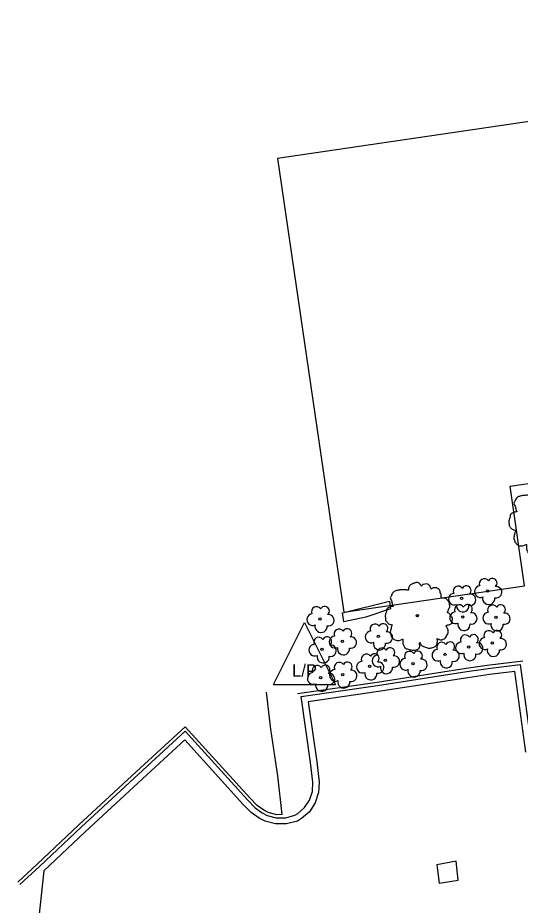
# Model space of a CAD drawing. Extents: x 2161152 to 2175754, y 602179 to 617749.
# Drawn here: x 2163456.9 to 2163537.9, y 606200.3 to 606343.4 of the extents above; entities that cross this region are included whole.
import ezdxf

# ---------------------------------------------------------------- set-up
doc = ezdxf.new("R2010")
doc.units = 0
for name, color, linetype in [('RD_EX_Bldg', 7, 'Continuous'), ('RD_EX_Conc_Curb', 7, 'Continuous'), ('RD_EX_Conc_Gutter', 7, 'Continuous'), ('RD_EX_Conc_Sidewalk', 7, 'Continuous'), ('RD_EX_DR_Inlet', 7, 'Continuous'), ('RD_EX_UT', 7, 'Continuous'), ('RD_EX_VEG', 7, 'Continuous')]:
    doc.layers.add(name, color=color, linetype=linetype)

msp = doc.modelspace()

# ---------------------------------------------------------------- linework, layer by layer
at = {"layer": 'RD_EX_Bldg'}
msp.add_lwpolyline([(2163498.74, 606320.78), (2163509.48, 606247.58), (2163538.63, 606251.86), (2163536.27, 606267.93), (2163632.21, 606282.02), (2163634.56, 606266.02), (2163663.95, 606270.34), (2163653.22, 606343.45), (2163498.74, 606320.78)], dxfattribs=at)
at = {"layer": 'RD_EX_Conc_Curb'}
for points in [[(2163457.2, 606203.69), (2163460.34, 606206.62), (2163467.07, 606212.93), (2163477.02, 606222.12), (2163483.86, 606228.43), (2163493.91, 606217.34), (2163495.17, 606216.05), (2163496.29, 606215.23), (2163497.1, 606214.83), (2163498.57, 606214.45), (2163500.1, 606214.46), (2163501.58, 606214.86), (2163502.04, 606215.13), (2163503.14, 606216.09), (2163503.95, 606217.31), (2163504.4, 606218.7), (2163504.47, 606220.17), (2163504.11, 606223.35), (2163502.57, 606234.01), (2163514.92, 606235.8), (2163529.3, 606238.03), (2163532.75, 606238.53), (2163537.89, 606239.18), (2163539.78, 606225.31)], [(2163538.32, 606239.73), (2163532.57, 606239.01), (2163529.22, 606238.52), (2163514.84, 606236.29), (2163502.01, 606234.44)], [(2163499.53, 606214.96), (2163498.64, 606214.95), (2163497.27, 606215.31), (2163496.55, 606215.66), (2163495.49, 606216.43), (2163494.28, 606217.68), (2163483.89, 606229.14), (2163476.68, 606222.49), (2163466.72, 606213.29), (2163460, 606206.98), (2163456.86, 606204.06)]]:
    msp.add_lwpolyline(points, dxfattribs=at)
at = {"layer": 'RD_EX_Conc_Gutter'}
msp.add_lwpolyline([(2163538.81, 606225.05), (2163537.04, 606238.06), (2163532.97, 606237.55), (2163529.45, 606237.04), (2163515.07, 606234.81), (2163503.71, 606233.17), (2163505.1, 606223.48), (2163505.47, 606220.2), (2163505.39, 606218.52), (2163504.86, 606216.87), (2163503.9, 606215.43), (2163502.63, 606214.32), (2163501.97, 606213.93), (2163500.24, 606213.46), (2163498.45, 606213.45), (2163496.75, 606213.89), (2163495.78, 606214.37), (2163494.51, 606215.29), (2163493.18, 606216.65), (2163483.8, 606227.01), (2163477.7, 606221.38), (2163467.75, 606212.19), (2163461.04, 606205.9), (2163460.26, 606198.45)], dxfattribs=at)
at = {"layer": 'RD_EX_Conc_Sidewalk'}
msp.add_lwpolyline([(2163499.53, 606214.96), (2163498.81, 606221.23), (2163497.69, 606228.72), (2163497, 606234.68)], dxfattribs=at)
at = {"layer": 'RD_EX_DR_Inlet'}
msp.add_lwpolyline([(2163524.44, 606206.89), (2163524.86, 606203.92), (2163527.91, 606204.39), (2163527.57, 606207.45), (2163524.44, 606206.89)], dxfattribs=at)
at = {"layer": 'RD_EX_UT'}
for p, q in [((2163498.13, 606235.92), (2163503.13, 606245.92)), ((2163503.13, 606245.92), (2163508.13, 606235.92)), ((2163498.13, 606235.92), (2163508.13, 606235.92))]:
    msp.add_line(p, q, dxfattribs=at)
at = {"layer": 'RD_EX_VEG'}
msp.add_lwpolyline([(2163513.02, 606246.78), (2163509.46, 606246.05), (2163509.27, 606247.49), (2163516.84, 606249.36), (2163516.97, 606248.13), (2163513.02, 606246.78)], dxfattribs=at)
for centre, radius in [((2163532.66, 606251.03), 0.188), ((2163528.46, 606249.82), 0.188), ((2163505.6, 606246.52), 0.188), ((2163521.33, 606247.02), 0.188), ((2163521.32, 606247.01), 0.000075), ((2163528.66, 606246.81), 0.188), ((2163534, 606246.77), 0.188), ((2163515.04, 606243.72), 0.188), ((2163505.95, 606241.59), 0.188), ((2163509.23, 606242.91), 0.188), ((2163529.61, 606241.97), 0.188), ((2163533.41, 606242.65), 0.188), ((2163525.8, 606240.78), 0.188), ((2163513.63, 606238.87), 0.188), ((2163516.16, 606239.86), 0.188), ((2163520.61, 606239.32), 0.188), ((2163509.28, 606237.55), 0.188), ((2163505.7, 606237.04), 0.188)]:
    msp.add_circle(centre, radius, dxfattribs=at)
for centre, radius, start, end in [((2163527.92, 606250.98), 0.813, 34.9763, 204.756), ((2163529.24, 606251.1), 0.746, 308.7626, 152.0467), ((2163531.48, 606250.91), 0.943, 96.4518, 294.734), ((2163532.12, 606252.19), 0.813, 34.9763, 204.756), ((2163533.44, 606252.31), 0.746, 308.7626, 152.0467), ((2163534.04, 606250.82), 0.914, 256.5667, 98.1046), ((2163527.29, 606249.7), 0.943, 96.4518, 294.734), ((2163529.84, 606249.61), 0.914, 256.5667, 98.1046), ((2163532.84, 606249.83), 0.988, 166.8827, 5.7589), ((2163505.06, 606247.68), 0.813, 34.9763, 204.756), ((2163506.38, 606247.8), 0.746, 308.7626, 152.0467), ((2163527.48, 606246.7), 0.943, 96.4518, 294.734), ((2163528.12, 606247.97), 0.813, 34.9763, 204.756), ((2163528.64, 606248.62), 0.988, 166.8827, 5.7589), ((2163529.44, 606248.09), 0.746, 308.7626, 152.0467), ((2163530.04, 606246.6), 0.914, 256.5667, 98.1046), ((2163532.83, 606246.65), 0.943, 96.4518, 294.734), ((2163533.46, 606247.93), 0.813, 34.9763, 204.756), ((2163534.78, 606248.05), 0.746, 308.7626, 152.0467), ((2163535.38, 606246.56), 0.914, 256.5667, 98.1046), ((2163504.43, 606246.4), 0.943, 96.4518, 294.734), ((2163506.98, 606246.31), 0.914, 256.5667, 98.1046), ((2163505.78, 606245.32), 0.988, 166.8827, 5.7589), ((2163508.69, 606244.07), 0.813, 34.9763, 204.756), ((2163510.01, 606244.18), 0.746, 308.7626, 152.0467), ((2163514.5, 606244.88), 0.813, 34.9763, 204.756), ((2163515.82, 606245), 0.746, 308.7626, 152.0467), ((2163528.84, 606245.62), 0.988, 166.8827, 5.7589), ((2163532.87, 606243.81), 0.813, 34.9763, 204.756), ((2163534.18, 606245.57), 0.988, 166.8827, 5.7589), ((2163534.19, 606243.92), 0.746, 308.7626, 152.0467), ((2163505.41, 606242.75), 0.813, 34.9763, 204.756), ((2163506.74, 606242.87), 0.746, 308.7626, 152.0467), ((2163508.05, 606242.79), 0.943, 96.4518, 294.734), ((2163510.61, 606242.7), 0.914, 256.5667, 98.1046), ((2163513.86, 606243.6), 0.943, 96.4518, 294.734), ((2163516.42, 606243.51), 0.914, 256.5667, 98.1046), ((2163529.07, 606243.13), 0.813, 34.9763, 204.756), ((2163530.4, 606243.24), 0.746, 308.7626, 152.0467), ((2163532.23, 606242.53), 0.943, 96.4518, 294.734), ((2163534.79, 606242.44), 0.914, 256.5667, 98.1046), ((2163504.78, 606241.48), 0.943, 96.4518, 294.734), ((2163507.33, 606241.38), 0.914, 256.5667, 98.1046), ((2163509.41, 606241.71), 0.988, 166.8827, 5.7589), ((2163515.22, 606242.52), 0.988, 166.8827, 5.7589), ((2163515.62, 606241.02), 0.813, 34.9763, 204.756), ((2163516.94, 606241.13), 0.746, 308.7626, 152.0467), ((2163525.26, 606241.94), 0.813, 34.9763, 204.756), ((2163526.59, 606242.06), 0.746, 308.7626, 152.0467), ((2163528.44, 606241.85), 0.943, 96.4518, 294.734), ((2163530.99, 606241.76), 0.914, 256.5667, 98.1046), ((2163506.14, 606240.4), 0.988, 166.8827, 5.7589), ((2163513.09, 606240.03), 0.813, 34.9763, 204.756), ((2163514.42, 606240.14), 0.746, 308.7626, 152.0467), ((2163514.98, 606239.74), 0.943, 96.4518, 294.734), ((2163517.54, 606239.65), 0.914, 256.5667, 98.1046), ((2163520.07, 606240.48), 0.813, 34.9763, 204.756), ((2163521.39, 606240.59), 0.746, 308.7626, 152.0467), ((2163524.63, 606240.67), 0.943, 96.4518, 294.734), ((2163527.18, 606240.57), 0.914, 256.5667, 98.1046), ((2163529.8, 606240.77), 0.988, 166.8827, 5.7589), ((2163533.59, 606241.45), 0.988, 166.8827, 5.7589), ((2163505.16, 606238.2), 0.813, 34.9763, 204.756), ((2163506.48, 606238.31), 0.746, 308.7626, 152.0467), ((2163508.74, 606238.71), 0.813, 34.9763, 204.756), ((2163510.06, 606238.82), 0.746, 308.7626, 152.0467), ((2163512.46, 606238.75), 0.943, 96.4518, 294.734), ((2163515.01, 606238.66), 0.914, 256.5667, 98.1046), ((2163516.34, 606238.66), 0.988, 166.8827, 5.7589), ((2163519.44, 606239.2), 0.943, 96.4518, 294.734), ((2163521.99, 606239.11), 0.914, 256.5667, 98.1046), ((2163525.99, 606239.59), 0.988, 166.8827, 5.7589), ((2163504.53, 606236.92), 0.943, 96.4518, 294.734), ((2163507.08, 606236.83), 0.914, 256.5667, 98.1046), ((2163508.1, 606237.43), 0.943, 96.4518, 294.734), ((2163510.66, 606237.34), 0.914, 256.5667, 98.1046), ((2163513.82, 606237.67), 0.988, 166.8827, 5.7589), ((2163520.79, 606238.12), 0.988, 166.8827, 5.7589), ((2163505.89, 606235.84), 0.988, 166.8827, 5.7589), ((2163509.46, 606236.35), 0.988, 166.8827, 5.7589)]:
    msp.add_arc(centre, radius, start, end, dxfattribs=at)
for points in [[(2163541.37, 606267.64), (2163541.14, 606267.66), (2163540.9, 606267.58), (2163540.71, 606267.51), (2163540.54, 606267.45), (2163540.37, 606267.38), (2163540.15, 606267.24), (2163539.98, 606267.09), (2163539.89, 606266.91), (2163539.85, 606266.74), (2163539.81, 606266.53), (2163539.81, 606266.4), (2163539.72, 606266.38), (2163539.6, 606266.4), (2163539.42, 606266.46), (2163539.23, 606266.46), (2163539.04, 606266.46), (2163538.78, 606266.44), (2163538.52, 606266.44), (2163538.31, 606266.4), (2163538.07, 606266.36), (2163537.79, 606266.27), (2163537.52, 606266.18), (2163537.3, 606265.99), (2163537.11, 606265.63), (2163537.02, 606265.37), (2163536.91, 606265.18), (2163537.02, 606264.85), (2163537.15, 606264.58), (2163537.17, 606264.43), (2163537.22, 606264.11), (2163537.3, 606263.95), (2163537.39, 606263.8), (2163537.34, 606263.78), (2163537.06, 606263.74), (2163536.83, 606263.66), (2163536.51, 606263.5), (2163536.34, 606263.33), (2163536.27, 606263.08), (2163536.25, 606262.82), (2163536.17, 606262.67), (2163536.12, 606262.47), (2163536.1, 606262.41), (2163536.06, 606262.17), (2163536.14, 606261.83), (2163536.16, 606261.57), (2163536.25, 606261.4), (2163536.36, 606261.27), (2163536.49, 606261.08), (2163536.79, 606260.91), (2163537.04, 606260.83), (2163537.19, 606260.82), (2163537.06, 606260.44), (2163537.02, 606260.18), (2163536.92, 606259.88), (2163536.92, 606259.82), (2163536.89, 606259.47), (2163537, 606259.22), (2163537.06, 606258.94), (2163537.19, 606258.77), (2163537.39, 606258.55), (2163537.64, 606258.38), (2163538.01, 606258.29), (2163538.31, 606258.3), (2163538.74, 606258.44), (2163538.93, 606258.49), (2163538.91, 606258.36), (2163538.93, 606258.08), (2163538.93, 606257.76), (2163539.04, 606257.52), (2163539.12, 606257.31), (2163539.23, 606257.12), (2163539.47, 606256.96), (2163539.77, 606256.9), (2163540.09, 606256.79), (2163540.43, 606256.73), (2163540.8, 606256.71), (2163541.25, 606256.82), (2163541.46, 606256.92), (2163541.53, 606257.05), (2163541.68, 606257.33), (2163541.65, 606257.5), (2163541.67, 606257.95), (2163541.74, 606257.82), (2163541.87, 606257.55), (2163542.25, 606257.33), (2163542.55, 606257.2), (2163542.9, 606257.09), (2163543.13, 606257.03), (2163543.48, 606257.09), (2163543.77, 606257.14), (2163544.05, 606257.24), (2163544.27, 606257.44), (2163544.4, 606257.65), (2163544.44, 606257.85), (2163544.5, 606258.14), (2163544.53, 606258.27)], [(2163521.42, 606252.39), (2163521.2, 606252.41), (2163520.96, 606252.34), (2163520.77, 606252.26), (2163520.6, 606252.21), (2163520.43, 606252.13), (2163520.21, 606252), (2163520.04, 606251.85), (2163519.94, 606251.66), (2163519.91, 606251.5), (2163519.87, 606251.29), (2163519.87, 606251.16), (2163519.78, 606251.14), (2163519.66, 606251.16), (2163519.48, 606251.21), (2163519.29, 606251.21), (2163519.1, 606251.21), (2163518.84, 606251.2), (2163518.58, 606251.2), (2163518.37, 606251.16), (2163518.13, 606251.12), (2163517.85, 606251.03), (2163517.58, 606250.93), (2163517.36, 606250.75), (2163517.17, 606250.39), (2163517.08, 606250.13), (2163516.96, 606249.94), (2163517.08, 606249.6), (2163517.21, 606249.34), (2163517.23, 606249.19), (2163517.28, 606248.87), (2163517.36, 606248.7), (2163517.45, 606248.55), (2163517.4, 606248.53), (2163517.11, 606248.5), (2163516.89, 606248.42), (2163516.57, 606248.25), (2163516.4, 606248.08), (2163516.33, 606247.84), (2163516.31, 606247.58), (2163516.23, 606247.43), (2163516.18, 606247.22), (2163516.16, 606247.17), (2163516.12, 606246.92), (2163516.2, 606246.58), (2163516.21, 606246.32), (2163516.31, 606246.15), (2163516.42, 606246.02), (2163516.55, 606245.84), (2163516.85, 606245.67), (2163517.1, 606245.59), (2163517.25, 606245.57), (2163517.11, 606245.2), (2163517.08, 606244.94), (2163516.98, 606244.64), (2163516.98, 606244.58), (2163516.95, 606244.22), (2163517.06, 606243.98), (2163517.11, 606243.7), (2163517.25, 606243.53), (2163517.45, 606243.3), (2163517.7, 606243.14), (2163518.07, 606243.04), (2163518.37, 606243.06), (2163518.8, 606243.19), (2163518.99, 606243.25), (2163518.97, 606243.12), (2163518.99, 606242.84), (2163518.99, 606242.52), (2163519.1, 606242.27), (2163519.18, 606242.07), (2163519.29, 606241.88), (2163519.53, 606241.71), (2163519.83, 606241.66), (2163520.15, 606241.54), (2163520.49, 606241.49), (2163520.86, 606241.47), (2163521.31, 606241.58), (2163521.52, 606241.67), (2163521.59, 606241.81), (2163521.74, 606242.09), (2163521.71, 606242.26), (2163521.72, 606242.71), (2163521.8, 606242.57), (2163521.93, 606242.31), (2163522.31, 606242.09), (2163522.61, 606241.96), (2163522.96, 606241.84), (2163523.19, 606241.79), (2163523.54, 606241.84), (2163523.82, 606241.9), (2163524.1, 606241.99), (2163524.33, 606242.2), (2163524.46, 606242.41), (2163524.5, 606242.61), (2163524.55, 606242.89), (2163524.59, 606243.02)], [(2163524.59, 606243.02), (2163524.54, 606243.15), (2163524.5, 606243.34), (2163524.55, 606243.32), (2163524.69, 606243.29), (2163524.89, 606243.19), (2163525.06, 606243.14), (2163525.3, 606243.15), (2163525.51, 606243.23), (2163525.85, 606243.44), (2163526.05, 606243.79), (2163526.26, 606244.09), (2163526.32, 606244.34), (2163526.28, 606244.5), (2163526.26, 606244.88), (2163526.11, 606245.07), (2163526.07, 606245.16), (2163526, 606245.46), (2163526.05, 606245.5), (2163526.26, 606245.54), (2163526.54, 606245.63), (2163526.75, 606245.72), (2163526.92, 606245.85), (2163526.97, 606246.02), (2163526.95, 606246.32), (2163526.99, 606246.62), (2163526.93, 606246.73), (2163526.86, 606246.85), (2163526.8, 606247), (2163526.69, 606247.11), (2163526.62, 606247.22), (2163526.54, 606247.3), (2163526.45, 606247.41), (2163526.32, 606247.5), (2163526.2, 606247.54), (2163526.17, 606247.65), (2163526.28, 606247.8), (2163526.32, 606247.88), (2163526.34, 606248.05), (2163526.5, 606248.31), (2163526.54, 606248.61), (2163526.5, 606248.93), (2163526.47, 606249.13), (2163526.35, 606249.34), (2163526.2, 606249.53), (2163526.11, 606249.66), (2163525.98, 606249.75), (2163525.74, 606249.85), (2163525.55, 606249.88), (2163525.29, 606249.88), (2163525.14, 606249.92), (2163525.15, 606249.96), (2163525.15, 606250.07), (2163525.15, 606250.28), (2163525.1, 606250.61), (2163524.99, 606250.99), (2163524.99, 606251.01), (2163524.91, 606251.2), (2163524.74, 606251.35), (2163524.61, 606251.42), (2163524.46, 606251.51), (2163524.27, 606251.53), (2163524.05, 606251.53), (2163523.84, 606251.5), (2163523.69, 606251.42), (2163523.56, 606251.33), (2163523.51, 606251.44), (2163523.43, 606251.66), (2163523.39, 606251.78), (2163523.28, 606251.91), (2163523.11, 606252.06), (2163522.77, 606252.15), (2163522.31, 606252.09), (2163522.08, 606251.94), (2163521.97, 606251.81), (2163521.93, 606251.91), (2163521.78, 606252.06), (2163521.71, 606252.19), (2163521.57, 606252.28), (2163521.46, 606252.36), (2163521.39, 606252.39)]]:
    msp.add_spline(points, degree=3, dxfattribs=at)

# ---------------------------------------------------------------- texts
at = {"layer": 'RD_EX_UT'}
msp.add_text('L/P', height=2, dxfattribs=at).set_placement((2163501.12, 606237.2))

doc.saveas('drawing.dxf')
